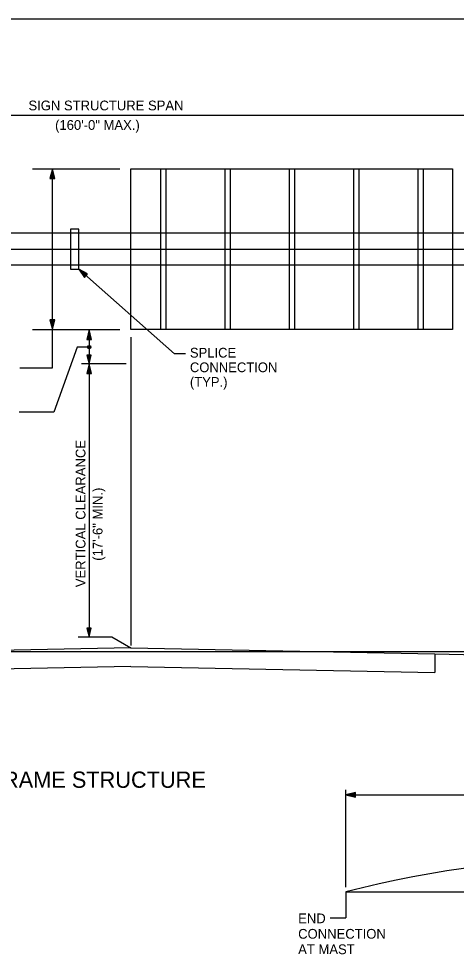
# Model space of a CAD drawing. Extents: x 640117 to 642655, y 297247 to 298435.
# Drawn here: x 641472.4 to 641607, y 297538.9 to 297826.5 of the extents above; entities that cross this region are included whole.
import ezdxf

# ---------------------------------------------------------------- set-up
doc = ezdxf.new("R2010")
doc.units = 0
for name, color, linetype in [('10', 7, 'Continuous'), ('2', 7, 'Continuous'), ('25', 7, 'Continuous'), ('47', 7, 'Continuous'), ('49', 7, 'Continuous'), ('50', 7, 'Continuous'), ('52', 7, 'Continuous'), ('53', 7, 'Continuous'), ('55', 7, 'Continuous')]:
    doc.layers.add(name, color=color, linetype=linetype)

msp = doc.modelspace()

# ---------------------------------------------------------------- linework, layer by layer
at = {"layer": '10'}
for p, q in [((641476.58, 297780.36), (641503.51, 297780.36)), ((641476.58, 297730.89), (641503.51, 297730.89)), ((641494.03, 297730.89), (641494.03, 297636.52)), ((641493.36, 297723.05), (641494.03, 297720.41)), ((641494.69, 297723.05), (641493.36, 297723.05)), ((641493.57, 297722.89), (641494.03, 297721.05)), ((641494.49, 297722.89), (641493.57, 297722.89)), ((641494.03, 297720.41), (641494.69, 297723.05)), ((641494.03, 297721.05), (641494.49, 297722.89)), ((641493.77, 297722.74), (641494.03, 297721.7)), ((641494.29, 297722.74), (641493.77, 297722.74)), ((641493.94, 297722.67), (641494.03, 297722.35)), ((641494.03, 297721.7), (641494.29, 297722.74)), ((641494.03, 297722.35), (641494.1, 297722.66)), ((641493.37, 297639.16), (641494.03, 297636.52)), ((641494.69, 297639.16), (641493.37, 297639.16)), ((641493.57, 297639.01), (641494.03, 297637.16)), ((641494.49, 297639.01), (641493.57, 297639.01)), ((641493.77, 297638.85), (641494.03, 297637.81)), ((641494.29, 297638.85), (641493.77, 297638.85)), ((641493.95, 297638.79), (641494.03, 297638.46)), ((641494.03, 297636.52), (641494.69, 297639.16)), ((641494.03, 297637.16), (641494.49, 297639.01)), ((641494.03, 297637.81), (641494.29, 297638.85)), ((641494.03, 297638.46), (641494.11, 297638.77))]:
    msp.add_line(p, q, dxfattribs=at)
msp.add_lwpolyline([(641490.7, 297636.52), (641500.97, 297636.52), (641506.9, 297633.09)], dxfattribs=at)
at = {"layer": '2'}
msp.add_line((640998.46, 297826.46), (641784.46, 297826.46), dxfattribs=at)
at = {"layer": '25'}
for p, q in [((641506.9, 297633.09), (641413.43, 297631.22)), ((641506.9, 297633.09), (641600.36, 297631.22)), ((641600.36, 297631.22), (641600.36, 297625.53)), ((641506.9, 297627.4), (641413.43, 297625.53)), ((641506.9, 297627.4), (641600.36, 297625.53))]:
    msp.add_line(p, q, dxfattribs=at)
at = {"layer": '47'}
msp.add_line((641600.36, 297631.22), (641687.14, 297629.48), dxfattribs=at)
at = {"layer": '49'}
for p, q in [((641506.9, 297780.36), (641605.84, 297780.36)), ((641506.9, 297730.89), (641506.9, 297780.36)), ((641516.02, 297780.36), (641516.02, 297730.89)), ((641517.67, 297780.36), (641517.67, 297730.89)), ((641535.81, 297780.36), (641535.81, 297730.89)), ((641537.46, 297780.36), (641537.46, 297730.89)), ((641555.6, 297780.36), (641555.6, 297730.89)), ((641557.25, 297780.36), (641557.25, 297730.89)), ((641575.38, 297780.36), (641575.38, 297730.89)), ((641577.03, 297780.36), (641577.03, 297730.89)), ((641595.17, 297780.36), (641595.17, 297730.89)), ((641596.82, 297780.36), (641596.82, 297730.89)), ((641605.84, 297780.36), (641605.84, 297730.89)), ((641605.84, 297730.89), (641506.9, 297730.89))]:
    msp.add_line(p, q, dxfattribs=at)
at = {"layer": '50'}
msp.add_line((641283.4, 297755.63), (641718.24, 297755.63), dxfattribs=at)
at = {"layer": '52'}
for p, q in [((641318.91, 297796.79), (641694.88, 297796.79)), ((641482.74, 297780.36), (641481.99, 297777.36)), ((641483.49, 297777.36), (641482.74, 297780.36)), ((641482.74, 297779.63), (641482.22, 297777.54)), ((641482.22, 297777.54), (641483.27, 297777.54)), ((641482.74, 297778.9), (641482.45, 297777.72)), ((641482.45, 297777.72), (641483.04, 297777.72)), ((641482.74, 297778.16), (641482.65, 297777.81)), ((641483.27, 297777.54), (641482.74, 297779.63)), ((641483.04, 297777.72), (641482.74, 297778.9)), ((641482.84, 297777.79), (641482.74, 297778.16)), ((641481.99, 297777.36), (641483.49, 297777.36)), ((641520.34, 297723.48), (641490.82, 297749.44)), ((641490.82, 297749.44), (641492.58, 297746.9)), ((641493.57, 297748.03), (641490.82, 297749.44)), ((641491.37, 297748.96), (641492.59, 297747.19)), ((641493.28, 297747.97), (641491.37, 297748.96)), ((641493, 297747.92), (641491.92, 297748.48)), ((641491.92, 297748.48), (641492.61, 297747.47)), ((641492.47, 297747.99), (641492.68, 297747.69)), ((641492.81, 297747.81), (641492.47, 297747.99)), ((641492.58, 297746.9), (641493.57, 297748.03)), ((641492.59, 297747.19), (641493.28, 297747.97)), ((641492.61, 297747.47), (641493, 297747.92)), ((641481.99, 297733.89), (641482.74, 297730.89)), ((641483.49, 297733.89), (641481.99, 297733.89)), ((641482.22, 297733.72), (641482.74, 297731.63)), ((641483.27, 297733.72), (641482.22, 297733.72)), ((641482.45, 297733.54), (641482.74, 297732.36)), ((641483.04, 297733.54), (641482.45, 297733.54)), ((641482.65, 297733.47), (641482.74, 297733.09)), ((641482.74, 297730.89), (641483.49, 297733.89)), ((641482.74, 297731.63), (641483.27, 297733.72)), ((641482.74, 297732.36), (641483.04, 297733.54)), ((641482.74, 297733.09), (641482.83, 297733.45)), ((641494.03, 297730.89), (641493.28, 297727.89)), ((641494.03, 297730.16), (641493.51, 297728.07)), ((641494.03, 297729.43), (641493.73, 297728.25)), ((641494.03, 297728.69), (641493.94, 297728.34)), ((641494.78, 297727.89), (641494.03, 297730.89)), ((641494.55, 297728.07), (641494.03, 297730.16)), ((641494.32, 297728.25), (641494.03, 297729.43)), ((641494.12, 297728.32), (641494.03, 297728.69)), ((641506.9, 297728.56), (641506.9, 297633.81)), ((641493.28, 297727.89), (641494.78, 297727.89)), ((641493.51, 297728.07), (641494.55, 297728.07)), ((641493.73, 297728.25), (641494.32, 297728.25)), ((641523.63, 297723.48), (641520.34, 297723.48)), ((641505.4, 297720.41), (641491.71, 297720.41)), ((641494.03, 297720.41), (641493.28, 297717.41)), ((641494.78, 297717.41), (641494.03, 297720.41)), ((641493.28, 297717.41), (641494.78, 297717.41)), ((641494.03, 297719.68), (641493.51, 297717.59)), ((641493.51, 297717.59), (641494.55, 297717.59)), ((641494.03, 297718.94), (641493.73, 297717.76)), ((641493.73, 297717.76), (641494.32, 297717.76)), ((641494.03, 297718.21), (641493.94, 297717.85)), ((641494.55, 297717.59), (641494.03, 297719.68)), ((641494.32, 297717.76), (641494.03, 297718.94)), ((641494.12, 297717.84), (641494.03, 297718.21)), ((641334.59, 297631.95), (641729.96, 297631.95)), ((641572.97, 297559.56), (641572.97, 297589.44)), ((641575.97, 297588.68), (641572.97, 297587.94)), ((641572.97, 297587.94), (641739.94, 297587.94)), ((641572.97, 297587.94), (641575.97, 297587.19)), ((641575.79, 297588.46), (641573.7, 297587.94)), ((641573.7, 297587.94), (641575.79, 297587.41)), ((641575.62, 297588.23), (641574.44, 297587.94)), ((641574.44, 297587.94), (641575.62, 297587.64)), ((641575.55, 297588.03), (641575.17, 297587.94)), ((641575.17, 297587.94), (641575.53, 297587.85)), ((641575.62, 297587.64), (641575.62, 297588.23)), ((641575.79, 297587.41), (641575.79, 297588.46)), ((641575.97, 297587.19), (641575.97, 297588.68)), ((641572.97, 297558.06), (641572.97, 297550.12)), ((641568.22, 297550.12), (641572.97, 297550.12))]:
    msp.add_line(p, q, dxfattribs=at)
for points in [[(641472.71, 297719.13), (641482.74, 297719.13), (641482.74, 297780.36)], [(641494.03, 297725.53), (641490.37, 297725.53), (641483.13, 297705.5), (641472.46, 297705.5)]]:
    msp.add_lwpolyline(points, dxfattribs=at)
for radius in [0.536, 0.268]:
    msp.add_circle((641494.03, 297725.53), radius, dxfattribs=at)
at = {"layer": '55'}
for p, q in [((641506.9, 297760.57), (641373.33, 297760.57)), ((641605.84, 297760.57), (641506.9, 297760.57)), ((641640.47, 297760.57), (641605.84, 297760.57)), ((641506.9, 297750.68), (641373.33, 297750.68)), ((641605.84, 297750.68), (641506.9, 297750.68)), ((641640.47, 297750.68), (641605.84, 297750.68)), ((641572.97, 297558.06), (641739.94, 297558.06))]:
    msp.add_line(p, q, dxfattribs=at)
msp.add_lwpolyline([(641490.82, 297761.81), (641488.34, 297761.81), (641488.34, 297749.44), (641490.82, 297749.44)], close=True, dxfattribs=at)
msp.add_arc((641656.45, 297234.09), 334.56, 75.5503, 104.4497, dxfattribs=at)

# ---------------------------------------------------------------- texts
at = {"layer": '10'}
for s, height, p in [('SPLICE', 2.992, (641525.03, 297722.31)), ('CONNECTION ', 2.9917, (641525.03, 297717.82)), ('(TYP.)', 2.992, (641525.03, 297713.33))]:
    msp.add_text(s, height=height, dxfattribs=at).set_placement(p)
at = {"layer": '53'}
for s, height, p in [('SIGN STRUCTURE SPAN', 3, (641475.36, 297798.29)), ('(160\'-0" MAX.)', 3, (641483.56, 297792.29)), ('FRAME STRUCTURE', 5, (641463.45, 297590.08)), ('END', 3, (641558.33, 297548.45)), ('CONNECTION', 3, (641558.33, 297543.7)), ('AT MAST', 3, (641558.33, 297538.95))]:
    msp.add_text(s, height=height, dxfattribs=at).set_placement(p)
for s, p in [('VERTICAL CLEARANCE', (641492.9, 297651.73)), ('(17\'-6" MIN.)', (641498.15, 297659.86))]:
    msp.add_text(s, height=3, rotation=90, dxfattribs=at).set_placement(p)

doc.saveas('drawing.dxf')
